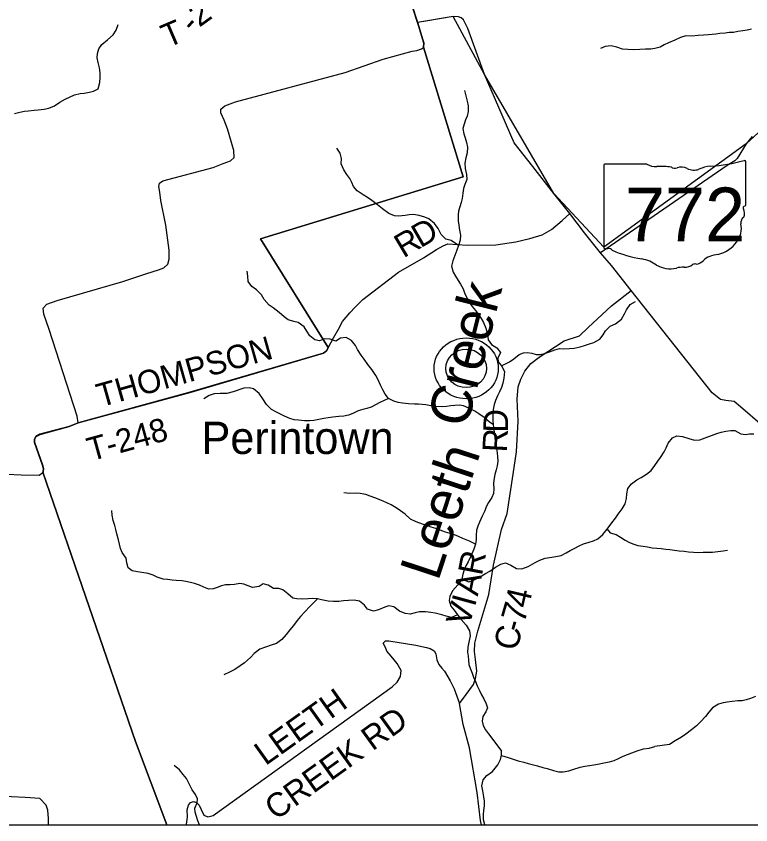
# Model space of a CAD drawing. Extents: x -139 to 835, y 0 to 440.
# Drawn here: x 126.7 to 183.8, y 185.4 to 248.2 of the extents above; entities that cross this region are included whole.
import ezdxf

# ---------------------------------------------------------------- set-up
doc = ezdxf.new("R2010")
doc.units = 0
for name, color, linetype in [('Default', 7, 'Continuous'), ('GM_X_County_Road', 7, 'Continuous'), ('GM_X_County_Road_Text', 7, 'Continuous'), ('GM_X_County_Text', 7, 'Continuous'), ('GM_X_Major_River', 7, 'Continuous'), ('GM_X_Minor_River', 7, 'Continuous'), ('GM_X_Minor_River_Text', 7, 'Continuous'), ('GM_X_State_Location', 7, 'Continuous'), ('GM_X_State_Route', 7, 'Continuous'), ('GM_X_State_Shield', 7, 'Continuous'), ('GM_X_Township_Road', 7, 'Continuous'), ('GM_X_Township_Road_Text', 7, 'Continuous'), ('GM_X_Unincorporated', 7, 'Continuous'), ('GM_X_Unincorporated_Location', 7, 'Continuous'), ('GM_X_Unincorporated_Text', 7, 'Continuous'), ('SH_Cut_Line', 7, 'Continuous')]:
    doc.layers.add(name, color=color, linetype=linetype)

msp = doc.modelspace()

# ---------------------------------------------------------------- linework, layer by layer
at = {"layer": 'Default'}
for p, q in [((157.887, 247.756), (154, 260.041)), ((160.66, 248.22), (157.887, 247.756)), ((163.094, 243.722), (160.66, 248.22)), ((168.465, 234.454), (163.094, 243.722)), ((187.302, 241.902), (183.419, 238.323)), ((183.419, 238.323), (172.348, 230.285)), ((172.348, 230.285), (168.465, 234.454))]:
    msp.add_line(p, q, dxfattribs=at)
at = {"layer": 'GM_X_County_Road'}
for points in [[(158.183, 245.707), (158.345, 245.818), (158.387, 246.142), (157.887, 247.756)], [(131.512, 216.624), (131.447, 217.149), (129.262, 223.885), (128.838, 225.091), (128.791, 225.561), (129.074, 225.873), (129.872, 226.146), (134.996, 227.636), (136.84, 228.256), (137.743, 228.535), (138.163, 228.688), (138.483, 228.962), (138.589, 229.359), (138.597, 230.059), (138.328, 232.004), (137.932, 233.914), (137.863, 234.578), (137.792, 235.002), (137.846, 235.266), (138.088, 235.445), (142.004, 236.477), (142.768, 236.794), (143.34, 236.993), (143.635, 237.255), (143.616, 237.799), (143.115, 239.481), (142.857, 240.171), (142.597, 240.729), (142.588, 241.019), (142.92, 241.28), (143.735, 241.585), (152.252, 243.883), (155.22, 244.902), (157.472, 245.533), (157.835, 245.59), (158.183, 245.707)], [(184.662, 216.441), (182.98, 217.87), (182.478, 218.298), (181.832, 218.365), (181.428, 218.454), (180.774, 218.956), (174.49, 226.913), (172.941, 228.872), (172.089, 229.856)], [(161.146, 194.807), (161.649, 195.526), (162.228, 196.304), (162.398, 196.76), (162.481, 197.326), (162.39, 198.232), (162.308, 198.86), (162.341, 199.5), (162.58, 200.45), (163.423, 203.3), (163.779, 205.565), (164.419, 208.357), (164.838, 209.595), (165.317, 212.654), (165.565, 214.389), (165.706, 216.776), (165.612, 218.478), (165.711, 219.442), (165.908, 220.031), (166.207, 220.643), (166.695, 221.241), (167.322, 221.741), (169.288, 222.999), (170.458, 223.397), (171.137, 224.041), (172.944, 225.735), (174.49, 226.913)], [(128.814, 213.028), (128.815, 213.06), (128.746, 213.352), (128.126, 215.116), (128.126, 215.323), (128.238, 215.569), (128.55, 215.742), (130.817, 216.345), (131.512, 216.624)], [(125.974, 212.655), (127.086, 212.601), (128.494, 212.56), (128.777, 212.774), (128.808, 212.834), (128.814, 213.028)], [(162.856, 185.387), (162.778, 185.712), (162.522, 187.889), (161.911, 191.362), (161.435, 193.178), (161.146, 194.807)], [(129.212, 185.387), (129.209, 185.87), (129.166, 186.522), (129.018, 186.922), (128.542, 187.422), (127.39, 187.518), (125.239, 187.607)]]:
    msp.add_lwpolyline(points, dxfattribs=at)
at = {"layer": 'GM_X_County_Text'}
for points in [[(67.578, 185.387), (138.399, 185.387), (135.965, 191.855), (128.77, 212.791), (128.801, 212.85), (128.808, 213.077), (128.738, 213.369), (128.118, 215.133), (128.118, 215.34), (128.23, 215.585), (128.542, 215.759), (130.81, 216.362), (131.505, 216.641), (140.104, 218.998), (150.572, 222.062), (150.829, 222.271), (150.94, 222.486), (145.692, 230.934), (161.421, 235.76), (158.337, 245.834), (158.379, 246.159), (157.88, 247.773), (156.946, 250.667)], [(156.946, 250.667), (157.88, 247.773), (158.379, 246.159), (158.337, 245.834), (161.421, 235.76), (145.692, 230.934), (150.94, 222.486), (150.829, 222.271), (150.572, 222.062), (140.104, 218.998), (131.505, 216.641), (130.81, 216.362), (128.542, 215.759), (128.23, 215.585), (128.118, 215.34), (128.118, 215.133), (128.738, 213.369), (128.808, 213.077), (128.801, 212.85), (128.77, 212.791), (135.965, 191.855), (138.399, 185.387), (295.458, 185.387)]]:
    msp.add_lwpolyline(points, dxfattribs=at)
at = {"layer": 'GM_X_Major_River'}
msp.add_lwpolyline([(183.829, 247.241), (183.486, 247.172), (183.167, 247.115), (182.76, 247.048), (182.43, 246.991), (182.099, 246.971), (181.782, 246.926), (181.375, 246.895), (181.057, 246.85), (180.498, 246.796), (180.104, 246.777), (179.685, 246.745), (179.202, 246.691), (178.72, 246.708), (178.312, 246.592), (177.865, 246.393), (177.393, 246.181), (177.048, 246.016), (176.728, 245.851), (176.321, 245.735), (176.003, 245.69), (175.597, 245.683), (175.152, 245.664), (174.67, 245.645), (174.213, 245.663), (173.82, 245.679), (173.365, 245.841), (172.922, 245.931), (172.452, 245.888), (172.107, 245.747)], dxfattribs=at)
at = {"layer": 'GM_X_Minor_River'}
for points in [[(130.515, 241.793), (131.227, 242.131), (131.659, 242.228), (131.977, 242.276), (132.396, 242.348), (132.714, 242.421), (133.057, 242.602), (133.198, 243.085), (133.223, 243.484), (133.236, 243.834), (133.16, 244.245), (133.071, 244.656), (132.995, 245.006), (133.008, 245.345), (133.11, 245.707), (133.364, 246.058), (133.797, 246.42), (134.229, 246.795), (134.471, 247.169), (134.611, 247.592)], [(161.529, 242.465), (161.63, 242.067), (161.744, 241.632), (161.808, 241.269), (161.807, 240.834), (161.744, 240.484), (161.616, 240.182), (161.413, 239.505), (161.476, 239.094), (161.577, 238.792), (161.691, 238.418), (161.768, 238.055), (161.742, 237.632), (161.64, 237.246), (161.551, 236.823), (161.576, 236.4), (161.677, 235.941), (161.715, 235.554), (161.563, 235.155), (161.448, 234.841), (161.41, 234.491), (161.359, 234.068), (161.282, 233.754), (161.168, 233.44), (161.053, 233.102), (161.027, 232.799), (161.04, 232.34), (161.09, 231.99), (161.154, 231.603), (161.23, 231.217), (161.192, 230.83), (161.064, 230.419), (160.937, 230.057), (160.784, 229.634), (160.619, 229.223), (160.529, 228.824), (160.656, 228.353), (160.821, 228.027), (161.037, 227.713), (161.228, 227.411), (161.418, 227.048), (161.52, 226.746), (161.748, 226.311), (161.926, 225.985), (162.129, 225.683), (162.383, 225.381), (162.612, 225.066), (162.828, 224.752), (163.018, 224.426), (163.196, 223.991), (163.31, 223.532), (163.373, 223.097), (163.627, 222.722), (164.034, 222.468), (164.339, 222.094), (164.11, 221.671), (164.16, 221.369), (164.414, 221.055), (164.643, 220.632), (164.592, 220.112), (164.503, 219.726), (164.401, 219.387), (164.261, 219.049), (164.108, 218.723), (163.943, 218.36), (163.841, 218.058), (163.764, 217.672), (163.726, 217.237), (163.738, 216.826), (163.751, 216.5), (163.801, 216.089), (163.852, 215.714), (163.953, 215.014), (164.017, 214.615), (164.067, 214.313), (164.105, 213.986), (164.118, 213.66), (164.067, 213.286), (163.99, 212.984), (163.901, 212.609), (163.812, 212.186), (163.774, 211.884), (163.799, 211.51), (163.773, 211.147), (163.646, 210.821), (163.404, 210.434), (163.226, 210.108), (163.099, 209.806), (162.908, 209.371), (162.692, 208.912), (162.564, 208.598), (162.475, 208.296), (162.449, 207.885), (162.449, 207.571), (162.386, 207.196), (162.246, 206.822), (162.029, 206.278), (161.813, 205.831), (161.647, 205.517), (161.495, 205.215), (161.406, 204.865)], [(126.574, 240.694), (126.994, 240.79), (127.337, 240.863), (127.667, 240.899), (128.1, 240.935), (128.417, 240.959), (128.862, 241.008), (129.244, 241.104), (129.663, 241.273), (130.083, 241.563), (130.515, 241.793)], [(161.064, 230.419), (160.505, 230.806), (160.073, 230.903), (159.717, 231.277), (159.476, 231.736), (159.209, 232.135), (158.765, 232.486), (158.447, 232.619), (158.002, 232.764), (157.557, 232.824), (157.24, 232.812), (156.909, 232.752), (156.401, 232.691), (156.083, 232.728), (155.651, 232.921), (155.168, 233.272), (154.762, 233.586), (154.33, 233.924), (153.987, 234.166), (153.656, 234.359), (153.186, 234.673), (152.907, 235.012), (152.767, 235.326), (152.627, 235.628), (152.386, 235.93), (152.145, 236.317), (151.942, 236.776), (151.967, 237.175), (151.879, 237.61), (151.612, 237.984)], [(163.751, 216.5), (163.471, 216.693), (163.052, 217.056), (162.658, 217.334), (162.341, 217.539), (161.87, 217.781), (161.464, 217.962), (161.146, 217.998), (160.777, 217.974), (160.46, 217.95), (160.142, 217.914), (159.786, 217.89), (159.29, 217.902), (158.922, 217.962), (158.515, 218.035), (157.956, 218.095), (157.638, 218.096), (157.181, 218.12), (156.71, 218.156), (156.38, 218.229), (156.049, 218.325), (155.617, 218.531), (155.376, 218.857), (155.186, 219.195), (154.995, 219.558), (154.817, 219.969), (154.652, 220.319), (154.335, 220.778), (154.017, 221.177), (153.725, 221.576), (153.509, 221.902), (153.23, 222.337), (153.052, 222.639), (152.747, 223.026), (152.341, 223.28), (151.896, 223.219), (151.527, 222.99), (151.082, 223.135), (150.663, 223.171), (150.256, 223.002), (149.9, 223.087), (149.519, 223.401), (149.291, 223.763), (149.062, 224.09), (148.605, 224.428), (148.261, 224.525), (147.842, 224.646), (147.512, 224.875), (147.143, 225.202), (146.673, 225.564), (146.343, 225.794), (145.962, 226.217), (145.746, 226.579), (145.378, 226.966), (144.996, 227.232), (144.73, 227.618), (144.692, 228.029), (144.654, 228.416)], [(164.414, 221.055), (165.025, 221.369), (165.355, 221.61), (165.788, 221.961), (166.106, 222.069), (166.423, 222.094), (166.754, 222.045), (167.097, 221.961), (167.415, 221.936), (167.745, 222.021), (168.127, 222.154), (168.559, 222.311), (168.902, 222.407), (169.232, 222.395), (169.69, 222.407), (170.046, 222.443), (170.529, 222.552), (170.859, 222.649), (171.254, 222.782), (171.584, 222.878), (172.042, 223.132), (172.296, 223.47), (172.487, 223.796), (172.843, 224.159), (173.275, 224.34), (173.721, 224.702), (173.975, 225.101), (174.128, 225.427), (174.408, 225.826), (174.827, 226.067)], [(155.617, 218.531), (155.287, 218.362), (154.943, 218.205), (154.613, 218.048), (154.27, 217.854), (153.952, 217.758), (153.634, 217.685), (153.265, 217.577), (152.859, 217.371), (152.515, 217.238), (152.159, 217.142), (151.765, 217.118), (151.295, 217.082), (150.926, 217.021), (150.609, 216.973), (150.214, 216.888), (149.833, 216.828), (149.503, 216.804), (149.096, 216.792), (148.626, 216.84), (148.295, 216.877), (147.952, 216.985), (147.558, 217.155), (147.24, 217.3), (146.923, 217.457), (146.542, 217.674), (146.135, 218.073), (145.868, 218.508), (145.576, 218.907), (145.144, 219.269), (144.801, 219.366), (144.382, 219.33), (143.568, 219.04), (143.06, 218.907), (142.551, 218.907), (142.094, 218.883), (141.687, 218.762), (141.28, 218.497)], [(161.316, 204.49), (161.875, 204.272), (162.219, 204.405), (162.689, 204.647), (163.16, 204.913), (163.49, 205.118), (163.935, 205.42), (164.342, 205.637), (164.724, 205.758), (165.143, 205.565), (165.575, 205.323), (165.994, 205.275), (166.49, 205.456), (167.024, 205.77), (167.393, 205.963), (167.812, 206.12), (168.308, 206.205), (168.626, 206.241), (169.033, 206.325), (169.427, 206.531), (169.745, 206.712), (170.113, 206.893), (170.444, 207.074), (170.787, 207.219), (171.207, 207.352), (171.563, 207.461), (171.881, 207.606), (172.275, 207.944), (172.618, 208.379), (172.974, 208.85), (173.254, 209.225), (173.483, 209.539), (173.776, 209.962), (174.005, 210.348), (174.132, 210.747), (174.145, 211.109), (174.221, 211.52), (174.514, 211.907), (174.921, 212.209), (175.251, 212.378), (175.671, 212.656), (176.027, 212.934), (176.332, 213.332), (176.549, 213.646), (176.752, 213.948), (177.045, 214.383), (177.198, 214.685), (177.363, 215.06), (177.706, 215.459), (178.024, 215.628), (178.482, 215.567), (178.965, 215.41), (179.397, 215.289), (179.816, 215.325), (180.236, 215.47), (180.732, 215.651), (181.138, 215.796), (181.482, 215.917), (181.838, 215.99), (182.219, 216.05), (182.537, 216.038), (182.994, 215.784), (183.363, 215.724), (183.68, 215.772), (184.011, 215.784)], [(162.386, 207.196), (161.915, 207.438), (161.394, 207.656), (161.077, 207.801), (160.759, 207.934), (160.429, 208.03), (160.06, 208.139), (159.298, 208.429), (158.929, 208.538), (158.599, 208.659), (158.268, 208.768), (157.785, 208.949), (157.328, 209.154), (156.909, 209.529), (156.566, 209.795), (156.235, 210.025), (155.829, 210.254), (155.486, 210.423), (155.028, 210.629), (154.571, 210.81), (154.202, 210.931), (153.859, 211.064), (153.427, 211.149), (153.096, 211.161), (152.626, 211.137), (152.169, 211.197)], [(160.984, 201.723), (160.514, 201.494), (160.095, 201.602), (159.764, 201.699), (159.256, 201.832), (158.913, 201.905), (158.493, 201.953), (158.023, 201.941), (157.705, 201.857), (157.311, 201.772), (156.93, 201.808), (156.485, 201.99), (156.053, 202.328), (155.646, 202.401), (155.329, 202.316), (154.858, 202.099), (154.464, 202.002), (154.007, 202.159), (153.765, 202.461), (153.371, 202.763), (152.965, 202.848), (152.507, 202.836), (152.126, 202.788), (151.77, 202.752), (151.363, 202.74), (150.931, 202.764), (150.423, 202.885), (150.105, 202.957), (149.698, 202.969), (149.38, 202.945), (148.935, 202.921), (148.516, 202.945), (148.198, 202.994), (147.792, 203.356), (147.423, 203.658), (147.106, 203.755), (146.686, 203.767), (146.28, 204.009), (145.886, 204.118), (145.568, 203.912), (145.059, 203.828), (144.716, 203.961), (144.386, 204.106), (144.068, 204.154), (143.649, 204.07), (143.293, 204.046), (142.962, 204.034), (142.644, 203.961), (142.327, 203.84), (142.009, 203.744), (141.666, 203.707), (141.272, 203.853), (140.929, 204.01), (140.547, 204.143), (140.23, 204.215), (139.886, 204.3), (139.556, 204.348), (139.124, 204.372), (138.806, 204.409), (138.45, 204.445), (138.107, 204.493), (137.65, 204.651), (137.332, 204.796), (136.951, 204.929), (136.468, 205.013), (136.137, 205.049), (135.705, 205.134), (135.388, 205.364), (135.286, 205.75), (135.235, 206.125), (134.931, 206.548), (134.804, 206.874), (134.728, 207.212), (134.639, 207.539), (134.525, 207.998), (134.436, 208.348), (134.36, 208.662), (134.246, 209.037), (134.157, 209.448), (134.132, 209.834)], [(172.618, 208.379), (172.847, 208.089), (173.317, 207.944), (173.647, 207.738), (174.016, 207.509), (174.346, 207.34), (174.689, 207.194), (175.007, 207.11), (175.426, 207.037), (175.744, 206.989), (176.125, 206.929), (176.481, 206.892), (176.812, 206.856), (177.168, 206.82), (177.485, 206.783), (177.854, 206.735), (178.21, 206.699), (178.604, 206.65), (178.934, 206.614), (179.316, 206.578), (179.684, 206.565), (180.078, 206.577), (180.396, 206.577), (180.79, 206.589), (181.209, 206.638), (181.629, 206.698), (181.959, 206.734)], [(161.406, 204.865), (161.316, 204.49), (161.011, 204.043), (160.591, 203.584), (160.4, 203.149), (160.337, 202.823), (160.476, 202.388), (160.718, 202.062), (160.984, 201.723), (161.276, 201.349), (161.67, 200.913), (161.924, 200.466), (161.975, 200.068), (161.86, 199.597), (161.784, 199.198), (161.758, 198.799), (161.809, 198.497), (161.834, 198.195), (161.872, 197.857), (161.973, 197.555), (162.126, 197.18), (162.24, 196.854), (162.379, 196.539), (162.519, 196.201), (162.697, 195.827), (162.862, 195.5), (163.027, 195.186), (163.217, 194.799), (163.319, 194.485), (163.192, 194.183), (162.963, 193.797), (162.912, 193.446), (162.988, 193.12), (163.165, 192.77), (163.394, 192.455), (163.661, 192.129), (164.419, 191.125)], [(150.105, 202.957), (149.507, 202.353), (149.113, 201.942), (148.782, 201.58), (148.541, 201.278), (148.235, 200.879), (147.968, 200.553), (147.688, 200.191), (147.345, 199.792), (146.913, 199.49), (146.518, 199.357), (146.061, 199.2), (145.641, 199.031), (145.184, 198.717), (144.904, 198.403), (144.446, 197.992), (144.09, 197.738), (143.696, 197.461), (143.276, 197.243), (142.831, 197.05)], [(184.139, 195.352), (183.745, 195.195), (183.427, 195.111), (183.097, 195.038), (182.766, 195.014), (182.334, 194.966), (181.953, 194.93), (181.622, 194.869), (181.266, 194.773), (180.809, 194.471), (180.529, 194.132), (180.262, 193.818), (179.893, 193.407), (179.562, 193.093), (179.168, 192.767), (178.723, 192.441), (178.38, 192.212), (177.896, 191.91), (177.451, 191.632), (176.331, 191.474)], [(163.114, 185.387), (163.018, 185.785), (163.007, 186.183), (163.046, 186.496), (163.085, 186.858), (163.086, 187.232), (163.037, 187.558), (162.95, 188.017), (162.888, 188.415), (162.991, 188.897), (163.258, 189.21), (163.703, 189.534), (164.124, 190.04), (164.341, 190.461), (164.405, 190.811), (164.419, 191.125)], [(164.4, 190.783), (164.912, 190.616), (165.381, 190.47), (165.71, 190.373), (166.141, 190.263), (166.471, 190.165), (166.8, 190.08), (167.193, 189.97), (167.624, 189.836), (167.953, 189.762), (168.435, 189.616), (168.866, 189.518), (169.208, 189.505), (169.64, 189.588), (170.021, 189.72), (170.516, 189.863), (170.871, 189.934), (171.252, 190.006), (171.582, 190.053), (172.026, 190.136), (172.356, 190.195), (172.8, 190.29), (173.156, 190.398), (173.499, 190.541), (173.855, 190.721), (174.185, 190.841), (174.528, 190.985), (174.96, 191.14), (175.43, 191.283), (175.886, 191.354), (176.331, 191.474)], [(140.946, 185.387), (140.808, 185.709), (140.707, 186.023), (140.607, 186.373), (140.583, 186.674), (140.762, 187.096), (140.788, 187.41), (140.637, 187.748), (140.372, 188.111), (139.919, 188.981), (139.679, 189.307), (139.376, 189.658), (138.971, 189.997)]]:
    msp.add_lwpolyline(points, dxfattribs=at)
at = {"layer": 'GM_X_State_Route'}
for points in [[(158.54, 247.865), (157.887, 247.756), (156.953, 250.65), (155.494, 255.352)], [(183.894, 238.904), (183.419, 238.323), (182.724, 237.191), (182.53, 237.016), (181.933, 236.644), (172.089, 229.856), (170.857, 231.404), (169.71, 232.914), (168.465, 234.454), (166.834, 236.551), (165.401, 238.405), (164.456, 240.542), (163.094, 243.722), (161.795, 247.303), (161.463, 247.97), (161.266, 248.12), (161.069, 248.199), (160.66, 248.22), (158.54, 247.865)]]:
    msp.add_lwpolyline(points, dxfattribs=at)
at = {"layer": 'GM_X_State_Shield'}
for p, q in [((172.348, 236.645), (172.348, 230.285)), ((175.691, 236.755), (172.457, 236.755)), ((183.393, 233.585), (183.393, 236.912)), ((183.392, 233.586), (183.393, 233.585))]:
    msp.add_line(p, q, dxfattribs=at)
for centre, major_axis, start_param, end_param in [((179.459, 245.425), (11.713, 0), 4.814394, 5.042369), ((183.27, 236.926), (0.123, 0), 6.141152, 7.989035), ((172.475, 236.659), (0.128, 0), 1.712693, 3.28349), ((176.462, 237.493), (1.241, 0), 4.042523, 4.731795), ((176.873, 233.184), (4.455, 0), 1.404758, 1.657858), ((177.885, 236.692), (0.358, 0), 3.836095, 5.185415), ((178.41, 235.957), (0.744, 0), 0.950623, 2.079405), ((179.371, 236.965), (0.896, 0), 4.081561, 5.145723), ((180.953, 234.812), (2.356, 0), 1.699011, 2.107814), ((183.365, 233.341), (0.19, 0), 1.883978, 3.671073), ((182.154, 232.921), (1.142, 0), 5.934695, 6.695948), ((183.262, 233.572), (0.132, 0), 5.05454, 6.418171), ((183.833, 232.193), (0.831, 0), 2.387724, 3.262537), ((180.115, 231.77), (2.93, 0), 5.101752, 6.440018), ((172.476, 230.272), (0.129, 0), 3.00124, 4.508301), ((172.495, 230.922), (0.985, 0), 4.665946, 4.897461), ((172.697, 229.919), (0.355, 0), 0.519207, 1.627899), ((177.182, 235.632), (8.458, 0), 4.195997, 4.488961), ((181.35, 228.5), (1.605, 0), 1.647645, 2.488434), ((174.66, 227.428), (2.646, 0), 0.823519, 1.323587), ((177.522, 229.887), (1.679, 0), 4.026481, 4.996735), ((178.615, 229.411), (0.895, 0), 4.691044, 5.507374), ((179.424, 228.795), (0.252, 0), 1.147584, 2.315152), ((179.317, 229.669), (0.947, 0), 4.937069, 5.64225), ((178.492, 227.688), (1.38, 0), 1.495662, 1.94098)]:
    msp.add_ellipse(centre, major_axis=major_axis, ratio=0.758645, start_param=start_param, end_param=end_param, dxfattribs=at)
at = {"layer": 'GM_X_Township_Road'}
msp.add_line((131.512, 216.624), (140.017, 218.955), dxfattribs=at)
for points in [[(151.148, 222.859), (151.349, 223.248), (151.731, 223.919), (152.061, 224.505), (152.326, 224.846), (152.635, 225.192), (153.045, 225.622), (153.635, 226.219), (156.396, 228.337), (158.336, 229.474), (159.369, 230.102), (159.88, 230.387), (160.249, 230.539), (161.731, 230.451), (163.962, 230.476), (165.51, 230.7), (166.616, 230.954), (167.557, 231.246), (168.297, 231.672), (169.116, 232.363), (169.71, 232.914)], [(140.017, 218.955), (140.111, 218.981), (150.579, 222.045), (150.836, 222.254), (150.947, 222.47), (151.148, 222.859)], [(139.926, 185.387), (139.94, 185.427), (139.997, 185.97), (139.976, 186.54), (140.083, 186.903), (140.255, 187.12), (140.484, 187.202), (140.713, 187.129), (140.904, 186.912), (141.076, 186.586), (141.286, 186.133), (141.582, 186.006), (141.992, 186.124), (155.923, 196.126), (156.295, 196.484), (156.554, 196.916), (156.598, 197.387), (156.312, 197.933), (155.823, 198.494), (155.51, 198.896), (155.386, 199.175), (155.212, 199.516), (155.392, 199.695), (155.659, 199.68), (157.763, 199.355), (158.574, 199.177), (158.865, 199.089), (159.168, 198.917), (159.305, 198.686), (159.389, 198.214), (159.537, 197.862), (159.775, 197.557), (159.988, 197.325), (160.424, 196.572), (160.722, 195.964), (161.146, 194.807)]]:
    msp.add_lwpolyline(points, dxfattribs=at)
at = {"layer": 'GM_X_Unincorporated'}
for major_axis in [(2.493, 0), (1.581, 0)]:
    msp.add_ellipse((161.665, 220.87), major_axis=major_axis, ratio=0.948307, dxfattribs=at)
at = {"layer": 'GM_X_Unincorporated_Location'}
msp.add_line((161.665, 220.87), (161.665, 220.87), dxfattribs=at)
at = {"layer": 'SH_Cut_Line'}
msp.add_lwpolyline([(67.578, 336.518), (67.578, 185.387), (295.458, 185.387), (295.458, 319.381), (267.909, 321.538), (228.151, 324.569), (207.436, 326.102), (194.287, 327.176), (177.155, 328.576), (171.559, 329.033), (160.688, 329.921), (158.444, 330.1), (105.67, 333.828), (92.493, 334.759)], close=True, dxfattribs=at)

# ---------------------------------------------------------------- texts
at = {"layer": 'GM_X_County_Road_Text'}
for s, height, rotation, p in [('D', 1.904, 89.14837, (164.898, 215.859)), ('R', 1.904, 86.94506, (164.816, 214.308)), ('R', 1.903, 79.25287, (162.881, 204.699)), ('A', 1.903, 78.54828, (162.56, 203.115)), ('I', 1.902, 74.68235, (162.334, 202.274)), ('4', 1.903, 76.9279, (166.502, 202.151)), ('V', 1.902, 73.81501, (161.882, 200.714)), ('7', 1.902, 73.86247, (166.166, 200.981)), ('-', 1.902, 73.72085, (165.956, 200.262)), ('C', 1.903, 76.38617, (165.612, 198.837))]:
    msp.add_text(s, height=height, rotation=rotation, dxfattribs=at).set_placement(p)
at = {"layer": 'GM_X_Minor_River_Text'}
for s, height, rotation, p in [('Creek', 3.1711, 75.82514, (161.711, 216.144)), ('Leeth', 3.169, 71.78207, (159.478, 204.258))]:
    msp.add_text(s, height=height, rotation=rotation, dxfattribs=at).set_placement(p)
at = {"layer": 'GM_X_State_Location'}
msp.add_text('772', height=0.00602, rotation=0.00001, dxfattribs=at).set_placement((175.506, 232.605))
for s in ['s', 'r']:
    msp.add_text(s, height=0.00602, dxfattribs=at).set_placement((177.746, 233.043))
at = {"layer": 'GM_X_State_Shield'}
msp.add_text('772', height=4.1897, dxfattribs=at).set_placement((173.99, 230.734))
at = {"layer": 'GM_X_Township_Road_Text'}
for s, height, rotation, p in [('2', 1.858, 35.79857, (140.926, 247.346)), ('T', 1.832, 23.17124, (138.469, 245.764)), ('-', 1.881, 48.58452, (140.506, 246.851)), ('D', 1.846, 30.06237, (158.111, 230.194)), ('R', 1.848, 30.65285, (156.789, 229.411)), ('THOMPSON', 1.819, 15.77855, (133.245, 217.84)), ('T-248', 1.8184, 15.41753, (132.5, 213.644)), ('LEETH', 1.8578, 35.54939, (146.068, 189.943)), ('CREEK RD', 1.8581, 35.72403, (146.87, 185.684))]:
    msp.add_text(s, height=height, rotation=rotation, dxfattribs=at).set_placement(p)
at = {"layer": 'GM_X_Unincorporated_Text'}
msp.add_text('Perintown', height=2.5099, rotation=0.00001, dxfattribs=at).set_placement((141.1, 214.215))

doc.saveas('drawing.dxf')
